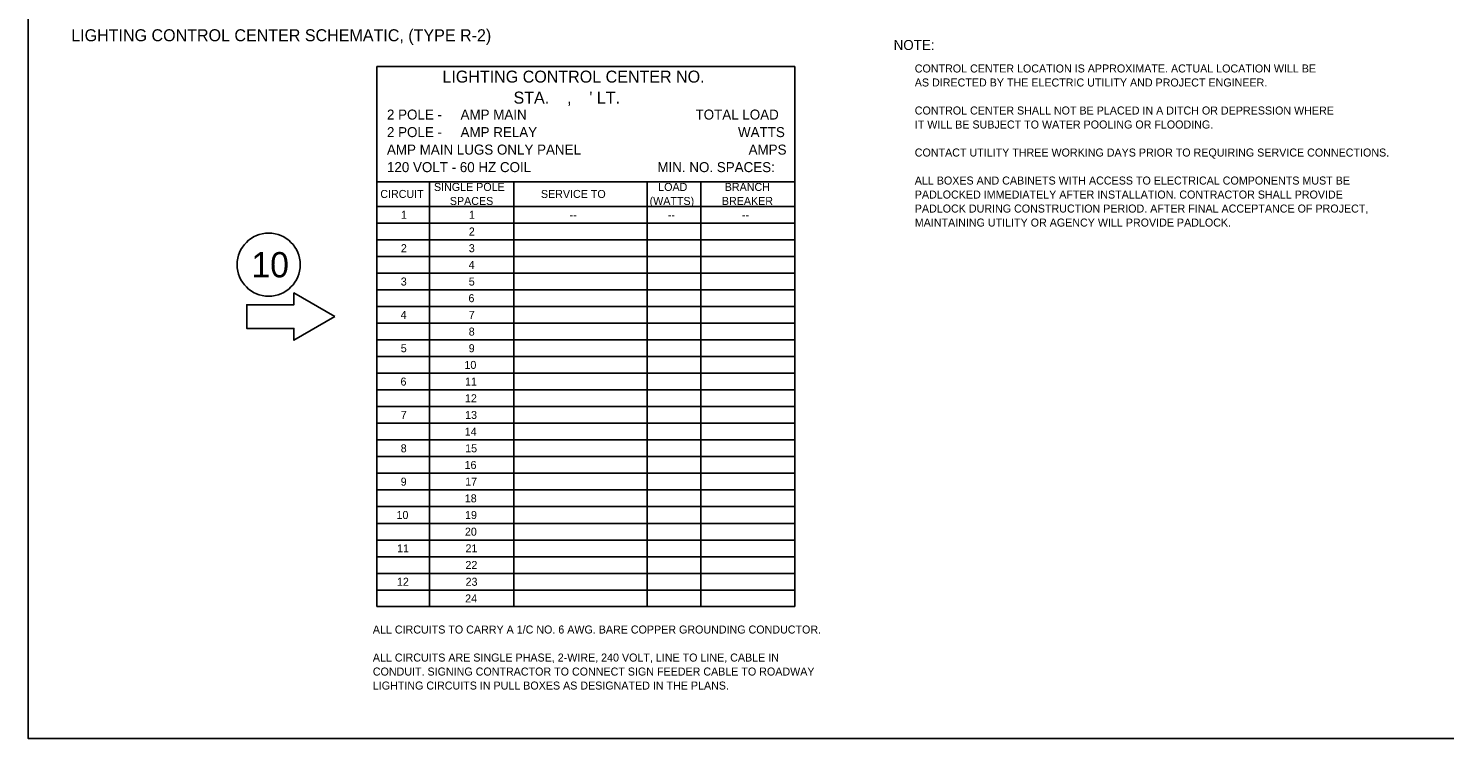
# Model space of a CAD drawing. Extents: x 99992 to 113392, y 99794 to 102182.
# Drawn here: x 110192 to 112316, y 99886 to 100951 of the extents above; entities that cross this region are included whole.
import ezdxf

# ---------------------------------------------------------------- set-up
doc = ezdxf.new("R2010")
doc.units = 0
for name, color, linetype in [('Border Organizer Shape', 7, 'Continuous'), ('Default', 7, 'Continuous'), ('QM Aggregate Gravel', 7, 'Continuous')]:
    doc.layers.add(name, color=color, linetype=linetype)

msp = doc.modelspace()

# ---------------------------------------------------------------- linework, layer by layer
at = {"layer": 'Border Organizer Shape'}
for p, q in [((110714.9, 100893.5), (110714.9, 100083.7)), ((110714.9, 100893.5), (111341.6, 100893.5)), ((111341.6, 100893.5), (111341.6, 100083.7)), ((110714.9, 100720.6), (111341.6, 100720.6)), ((110794.1, 100720.6), (110794.1, 100083.7)), ((110920.6, 100720.6), (110920.6, 100083.7)), ((111120.4, 100720.6), (111120.4, 100083.7)), ((111200.6, 100720.6), (111200.6, 100083.7)), ((110714.9, 100683.5), (111341.6, 100683.5)), ((110714.9, 100658.5), (111341.6, 100658.5)), ((110714.9, 100633.5), (111341.6, 100633.5)), ((110714.9, 100608.5), (111341.6, 100608.5)), ((110714.9, 100583.5), (111341.6, 100583.5)), ((110714.9, 100558.5), (111341.6, 100558.5)), ((110714.9, 100533.5), (111341.6, 100533.5)), ((110714.9, 100533.5), (111341.6, 100533.5)), ((110714.9, 100508.5), (111341.6, 100508.5)), ((110714.9, 100483.5), (111341.6, 100483.5)), ((110714.9, 100458.5), (111341.6, 100458.5)), ((110714.9, 100433.5), (111341.6, 100433.5)), ((110714.9, 100408.5), (111341.6, 100408.5)), ((110714.9, 100383.5), (111341.6, 100383.5)), ((110714.9, 100358.5), (111341.6, 100358.5)), ((110714.9, 100333.5), (111341.6, 100333.5)), ((110714.9, 100308.5), (111341.6, 100308.5)), ((110714.9, 100283.5), (111341.6, 100283.5)), ((110714.9, 100258.5), (111341.6, 100258.5)), ((110714.9, 100233.5), (111341.6, 100233.5)), ((110714.9, 100208.5), (111341.6, 100208.5)), ((110714.9, 100183.5), (111341.6, 100183.5)), ((110714.9, 100158.5), (111341.6, 100158.5)), ((110714.9, 100133.4), (111341.6, 100133.4)), ((110714.9, 100108.5), (111341.6, 100108.5)), ((110714.9, 100083.7), (111341.6, 100083.7))]:
    msp.add_line(p, q, dxfattribs=at)
at = {"layer": 'Default'}
msp.add_lwpolyline([(110192.2, 102085.3), (113391.9, 102085.3), (113391.9, 99885.7), (110192.2, 99885.7)], close=True, dxfattribs=at)
at = {"layer": 'QM Aggregate Gravel'}
msp.add_lwpolyline([(110652, 100518.4), (110590.6, 100482.9), (110590.6, 100500.7), (110519.7, 100500.7), (110519.7, 100536.1), (110590.6, 100536.1), (110590.6, 100553.9)], close=True, dxfattribs=at)
msp.add_circle((110552.7, 100596.3), 47.3, dxfattribs=at)

# ---------------------------------------------------------------- texts
at = {"layer": 'Border Organizer Shape'}
for s, height, p in [('LIGHTING CONTROL CENTER SCHEMATIC, (TYPE R-2)', 18, (110256.6, 100931.2)), ('NOTE:', 15, (111490, 100918.1)), ('LIGHTING CONTROL CENTER NO.', 18, (110813.3, 100869.2)), ('CONTROL CENTER LOCATION IS APPROXIMATE. ACTUAL LOCATION WILL BE', 12, (111521.7, 100884.4)), ('AS DIRECTED BY THE ELECTRIC UTILITY AND PROJECT ENGINEER.', 12, (111521.7, 100863.4)), ("STA.    ,    ' LT.", 18, (110919.9, 100837.7)), ('2 POLE -     AMP MAIN', 15, (110730.1, 100813.8)), ('TOTAL LOAD', 15, (111192.9, 100813.8)), ('CONTROL CENTER SHALL NOT BE PLACED IN A DITCH OR DEPRESSION WHERE', 12, (111521.7, 100821.4)), ('2 POLE -     AMP RELAY', 15, (110730.1, 100787.5)), ('WATTS', 15, (111256.6, 100787.5)), ('IT WILL BE SUBJECT TO WATER POOLING OR FLOODING.', 12, (111521.7, 100800.4)), ('AMP MAIN LUGS ONLY PANEL', 15, (110730.1, 100761.3)), ('AMPS', 15, (111272.5, 100761.3)), ('CONTACT UTILITY THREE WORKING DAYS PRIOR TO REQUIRING SERVICE CONNECTIONS.', 12, (111521.7, 100758.4)), ('120 VOLT - 60 HZ COIL', 15, (110730.1, 100735)), ('MIN. NO. SPACES:', 15, (111135.7, 100735)), ('CIRCUIT', 12, (110720.1, 100696.3)), ('SINGLE POLE', 12, (110800.6, 100706.8)), ('SERVICE TO', 12, (110961, 100696.3)), ('LOAD', 12, (111136.9, 100706.8)), ('BRANCH', 12, (111236.7, 100706.8)), ('ALL BOXES AND CABINETS WITH ACCESS TO ELECTRICAL COMPONENTS MUST BE', 12, (111521.7, 100716.4)), ('SPACES', 12, (110824.4, 100685.8)), ('(WATTS)', 12, (111124, 100685.8)), ('BREAKER', 12, (111232.4, 100685.8)), ('PADLOCKED IMMEDIATELY AFTER INSTALLATION. CONTRACTOR SHALL PROVIDE', 12, (111521.7, 100695.4)), ('1', 12, (110751.1, 100665)), ('1', 12, (110853.1, 100665)), ('--', 12, (111004, 100665)), ('--', 12, (111151.3, 100665)), ('--', 12, (111262.4, 100665)), ('PADLOCK DURING CONSTRUCTION PERIOD. AFTER FINAL ACCEPTANCE OF PROJECT,', 12, (111521.7, 100674.4)), ('2', 12, (110852.9, 100640)), ('MAINTAINING UTILITY OR AGENCY WILL PROVIDE PADLOCK.', 12, (111521.7, 100653.4)), ('2', 12, (110751, 100615)), ('3', 12, (110852.8, 100615)), ('4', 12, (110852.6, 100590)), ('3', 12, (110750.8, 100565)), ('5', 12, (110852.8, 100565)), ('6', 12, (110852.3, 100540)), ('4', 12, (110750.6, 100515)), ('7', 12, (110852.8, 100515)), ('8', 12, (110852.7, 100490)), ('5', 12, (110750.8, 100465)), ('9', 12, (110852.7, 100465)), ('10', 12, (110846.3, 100440)), ('6', 12, (110750.4, 100415)), ('11', 12, (110847.2, 100415)), ('12', 12, (110847.1, 100390)), ('7', 12, (110750.8, 100365)), ('13', 12, (110847.3, 100365)), ('14', 12, (110846.7, 100340)), ('8', 12, (110750.7, 100315)), ('15', 12, (110847.4, 100315)), ('16', 12, (110846.5, 100290)), ('9', 12, (110750.7, 100265)), ('17', 12, (110847.4, 100265)), ('18', 12, (110846.8, 100240)), ('10', 12, (110744.4, 100215)), ('19', 12, (110847.2, 100215)), ('20', 12, (110847, 100190)), ('11', 12, (110745.3, 100165)), ('21', 12, (110847.9, 100165)), ('22', 12, (110847.8, 100140)), ('12', 12, (110745.1, 100114.9)), ('23', 12, (110848, 100114.9)), ('24', 12, (110847.4, 100089.9)), ('ALL CIRCUITS TO CARRY A 1/C NO. 6 AWG. BARE COPPER GROUNDING CONDUCTOR.', 12, (110708.9, 100043.3)), ('ALL CIRCUITS ARE SINGLE PHASE, 2-WIRE, 240 VOLT, LINE TO LINE, CABLE IN', 12, (110708.9, 100001.3)), ('CONDUIT. SIGNING CONTRACTOR TO CONNECT SIGN FEEDER CABLE TO ROADWAY', 12, (110708.9, 99980.3)), ('LIGHTING CIRCUITS IN PULL BOXES AS DESIGNATED IN THE PLANS.', 12, (110708.9, 99959.3))]:
    msp.add_text(s, height=height, dxfattribs=at).set_placement(p)
at = {"layer": 'QM Aggregate Gravel'}
msp.add_text('10', height=37.84, dxfattribs=at).set_placement((110526.8, 100577.3))

doc.saveas('drawing.dxf')
